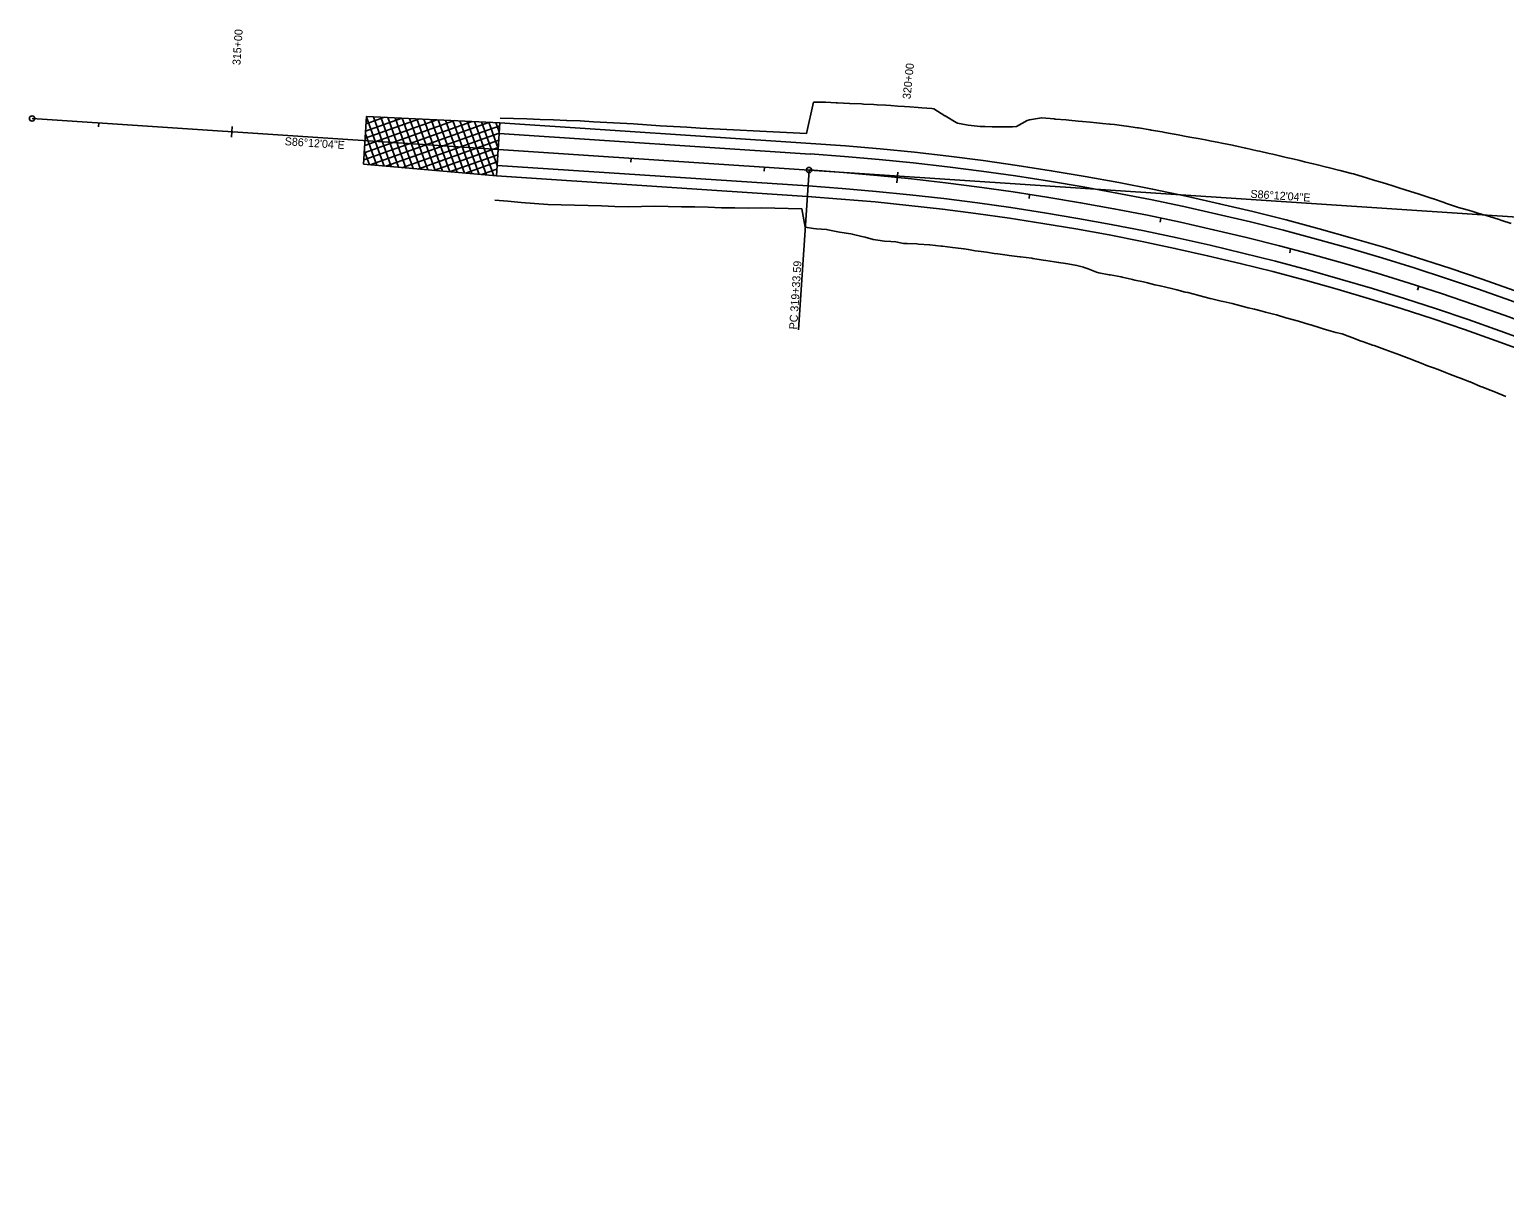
# Model space of a CAD drawing. Extents: x 881426 to 887360, y 1564404 to 1567430.
# Drawn here: x 881426 to 882531, y 1566404 to 1567265 of the extents above; entities that cross this region are included whole.
import ezdxf

# ---------------------------------------------------------------- set-up
doc = ezdxf.new("R2010")
doc.units = 0
for name, color, linetype in [('R_Axis', 7, 'Continuous'), ('R_Horz Alg', 7, 'Continuous'), ('R_Horz Alg Annot', 7, 'Continuous'), ('R_Proposed Const Limits_Fill', 7, 'Continuous'), ('R_Proposed Road_Lane', 7, 'Continuous'), ('R_Proposed Road_Shoulder', 7, 'Continuous')]:
    doc.layers.add(name, color=color, linetype=linetype)

msp = doc.modelspace()

# ---------------------------------------------------------------- linework, layer by layer
at = {"layer": 'R_Axis'}
for p, q in [((881676.1, 1567167.2), (881757.3, 1567196.1)), ((881676.4, 1567172.6), (881744.1, 1567196.7)), ((881676.8, 1567178.1), (881731, 1567197.3)), ((881677.1, 1567183.5), (881717.9, 1567198)), ((881677.5, 1567188.9), (881704.7, 1567198.6)), ((881677.9, 1567194.4), (881691.6, 1567199.2)), ((881678.2, 1567199.8), (881678.5, 1567199.9)), ((881691.3, 1567162.6), (881678.2, 1567199.3)), ((881696.7, 1567162.2), (881683.4, 1567199.6)), ((881702.2, 1567161.7), (881688.8, 1567199.4)), ((881707.7, 1567161.2), (881694.2, 1567199.1)), ((881713.2, 1567160.7), (881699.6, 1567198.9)), ((881718.7, 1567160.2), (881705, 1567198.6)), ((881724.1, 1567159.7), (881710.4, 1567198.3)), ((881729.6, 1567159.2), (881715.8, 1567198.1)), ((881735.1, 1567158.7), (881721.2, 1567197.8)), ((881740.6, 1567158.3), (881726.6, 1567197.6)), ((881746.1, 1567157.8), (881732, 1567197.3)), ((881751.5, 1567157.3), (881737.4, 1567197)), ((881757, 1567156.8), (881742.8, 1567196.8)), ((881762.5, 1567156.3), (881748.2, 1567196.5)), ((881768, 1567155.8), (881753.6, 1567196.3)), ((881685.8, 1567163.1), (881677.4, 1567186.8)), ((881680.8, 1567163.6), (881770.4, 1567195.5)), ((881692.7, 1567162.5), (881778, 1567192.8)), ((881704.7, 1567161.4), (881777.6, 1567187.4)), ((881773.5, 1567155.3), (881759, 1567196)), ((881776, 1567163.1), (881764.4, 1567195.7)), ((881776.8, 1567175.7), (881769.8, 1567195.5)), ((881777.7, 1567188.2), (881775.2, 1567195.2)), ((881680.3, 1567163.6), (881676.5, 1567174.2)), ((881716.6, 1567160.4), (881777.3, 1567182)), ((881728.6, 1567159.3), (881776.9, 1567176.5)), ((881740.5, 1567158.3), (881776.5, 1567171.1)), ((881752.4, 1567157.2), (881776.2, 1567165.7)), ((881764.4, 1567156.2), (881775.8, 1567160.2))]:
    msp.add_line(p, q, dxfattribs=at)
at = {"layer": 'R_Horz Alg'}
msp.add_line((881427.5, 1567198.3), (882009.9, 1567159.6), dxfattribs=at)
msp.add_arc((881883.4, 1565254), 1909.9, 37.4722, 86.2011, dxfattribs=at)
at = {"layer": 'R_Horz Alg Annot'}
msp.add_line((882009.9, 1567159.6), (882872.9, 1567102.3), dxfattribs=at)
for points in [[(881477.3, 1567192), (881477.5, 1567195)], [(881577.5, 1567192.4), (881577, 1567184.4)], [(881676.8, 1567178.8), (881677, 1567181.7)], [(881776.6, 1567172.1), (881776.8, 1567175.1)], [(881876.4, 1567165.5), (881876.6, 1567168.5)], [(881976.2, 1567158.9), (881976.4, 1567161.9)], [(882009.9, 1567159.6), (882001.9, 1567039.9)], [(882076.5, 1567158.1), (882075.7, 1567150.1)], [(882174.8, 1567138.4), (882175.2, 1567141.4)], [(882273, 1567120.6), (882273.6, 1567123.5)], [(882370.2, 1567097.7), (882370.9, 1567100.6)], [(882466, 1567069.6), (882466.9, 1567072.5)]]:
    msp.add_lwpolyline(points, dxfattribs=at)
for centre in [(881427.5, 1567198.3), (882009.9, 1567159.6)]:
    msp.add_circle(centre, 2, dxfattribs=at)
at = {"layer": 'R_Proposed Const Limits_Fill'}
for points in [[(881778.4, 1567198.6), (881788.4, 1567198.3), (881798.4, 1567198), (881808.4, 1567197.6), (881818.4, 1567197.3), (881828.2, 1567196.9), (881828.4, 1567196.9), (881838.4, 1567196.5), (881848.3, 1567195.8), (881858.3, 1567195.4), (881868.3, 1567194.9), (881878.3, 1567194.3), (881888.3, 1567193.5), (881898.2, 1567192.8), (881908.2, 1567192.3), (881918.2, 1567191.8), (881928.2, 1567191.1), (881938.2, 1567190.5), (881948.2, 1567190.1), (881958.2, 1567189.6), (881968.1, 1567189), (881978.1, 1567188.5), (881988.1, 1567188), (881998.1, 1567187.6), (882008.1, 1567187.1), (882013.3, 1567210.5), (882019.9, 1567210.4), (882022.3, 1567210.4), (882030.1, 1567210.1), (882031.3, 1567210), (882040.3, 1567209.6), (882040.4, 1567209.6), (882049.3, 1567209.2), (882050.7, 1567209.1), (882058.4, 1567208.7), (882060.9, 1567208.6), (882067.4, 1567208.2), (882071.2, 1567208), (882076.4, 1567207.6), (882081.5, 1567207.3), (882085.4, 1567207), (882091.7, 1567206.5), (882094.4, 1567206.3), (882102, 1567205.7), (882103.4, 1567205.6), (882111.7, 1567200.4), (882111.9, 1567200.2), (882120.3, 1567195.2), (882121.3, 1567194.7), (882129.2, 1567193.4), (882131.5, 1567193.1), (882138.1, 1567192.2), (882141.7, 1567192.2), (882147.1, 1567192.1), (882152, 1567192.1), (882156.2, 1567192.1), (882162.3, 1567192.1), (882165.3, 1567192.2), (882173.4, 1567196.9), (882175.2, 1567197.4), (882184.1, 1567198.7), (882184.5, 1567198.7), (882193.6, 1567198), (882194.4, 1567197.9), (882202.6, 1567197.2), (882204.7, 1567197), (882211.7, 1567196.4), (882215, 1567196.1), (882220.7, 1567195.5), (882225.3, 1567195.1), (882229.8, 1567194.6), (882235.2, 1567194.1), (882235.6, 1567194.1), (882238.8, 1567193.7), (882245.9, 1567192.8), (882247.8, 1567192.5), (882256.1, 1567191.3), (882256.8, 1567191.2), (882265.7, 1567189.7), (882266.3, 1567189.6), (882274.7, 1567188.2), (882276.5, 1567187.8), (882283.6, 1567186.6), (882286.7, 1567186), (882292.5, 1567184.9), (882296.8, 1567184.1), (882301.5, 1567183.3), (882307, 1567182.2), (882310.4, 1567181.5), (882317.1, 1567180.2), (882319.3, 1567179.8), (882327.3, 1567178.2), (882328.2, 1567178), (882337, 1567176.1), (882337.4, 1567176), (882345.9, 1567174.1), (882347.5, 1567173.8), (882354.8, 1567172.1), (882357.6, 1567171.5), (882363.6, 1567170.1), (882367.6, 1567169.1), (882372.5, 1567168), (882377.7, 1567166.8), (882381.3, 1567165.9), (882387.8, 1567164.3), (882390.1, 1567163.7), (882397.8, 1567161.8), (882399, 1567161.6), (882407.8, 1567159.4), (882407.9, 1567159.3), (882416.6, 1567157.1), (882417.9, 1567156.7), (882425.3, 1567154.5), (882427.8, 1567153.8), (882434, 1567151.9), (882437.7, 1567150.8), (882442.7, 1567149.2), (882447.6, 1567147.7), (882451.3, 1567146.5), (882457.5, 1567144.6), (882460, 1567143.8), (882467.3, 1567141.5), (882468.7, 1567141), (882477.1, 1567138.2), (882477.3, 1567138.2), (882485.9, 1567135.2), (882486.9, 1567134.9), (882494.5, 1567132.3), (882496.7, 1567131.6), (882503.2, 1567129.7), (882506.7, 1567128.7), (882511.9, 1567127.1), (882516.6, 1567125.7), (882520.6, 1567124.5), (882526.5, 1567122.7), (882529.3, 1567121.8), (882536.3, 1567119.5)], [(881774.3, 1567137), (881784.2, 1567136.2), (881794.2, 1567135.4), (881804.2, 1567134.6), (881814.2, 1567133.9), (881824, 1567133.6), (881824.2, 1567133.6), (881834.2, 1567133.3), (881844.2, 1567133), (881854.2, 1567132.7), (881864.2, 1567132.4), (881874.2, 1567132.1), (881884.2, 1567132.4), (881894.2, 1567132.5), (881904.3, 1567132.3), (881914.3, 1567132.1), (881924.3, 1567132), (881934.3, 1567131.8), (881944.3, 1567131.4), (881954.3, 1567131.3), (881964.3, 1567131.1), (881974.3, 1567131.2), (881984.3, 1567131), (881994.3, 1567130.8), (882004.4, 1567130.6), (882007, 1567116.8), (882013.3, 1567115.8), (882015.6, 1567115.6), (882023, 1567115.1), (882024.1, 1567114.9), (882032.6, 1567113.2), (882032.6, 1567113.1), (882041.1, 1567111.8), (882042.3, 1567111.7), (882049.5, 1567109.9), (882051.9, 1567109.3), (882057.9, 1567107.7), (882061.5, 1567107.2), (882066.4, 1567106.4), (882071.2, 1567106), (882074.9, 1567105.8), (882080.8, 1567104.7), (882083.4, 1567104.6), (882090.6, 1567104.3), (882092, 1567104.2), (882100.3, 1567103.6), (882100.5, 1567103.6), (882109, 1567102.7), (882110, 1567102.6), (882117.5, 1567101.6), (882119.7, 1567101.4), (882126, 1567100.6), (882129.4, 1567100), (882134.5, 1567099.2), (882139, 1567098.6), (882142.9, 1567098), (882148.7, 1567097.2), (882151.4, 1567096.8), (882158.3, 1567095.9), (882159.9, 1567095.7), (882168, 1567094.7), (882168.4, 1567094.6), (882176.9, 1567093.5), (882177.7, 1567093.3), (882185.4, 1567092.2), (882187.3, 1567091.9), (882193.8, 1567090.9), (882197, 1567090.4), (882202.3, 1567089.5), (882206.6, 1567088.8), (882210.7, 1567088.1), (882215.7, 1567086.8), (882216.1, 1567086.7), (882219, 1567085.6), (882225.4, 1567083.1), (882227.1, 1567082.7), (882234.9, 1567081.1), (882235.5, 1567081), (882243.9, 1567079.5), (882244.5, 1567079.3), (882252.3, 1567077.5), (882254, 1567077.1), (882260.7, 1567075.8), (882263.5, 1567075.1), (882269, 1567073.7), (882273, 1567072.8), (882277.3, 1567071.9), (882282.5, 1567070.6), (882285.6, 1567069.8), (882291.9, 1567068.2), (882293.9, 1567067.8), (882301.4, 1567065.9), (882302.2, 1567065.7), (882310.5, 1567063.4), (882310.8, 1567063.4), (882318.8, 1567061.4), (882320.2, 1567061.1), (882327.1, 1567059.5), (882329.7, 1567058.8), (882335.4, 1567057.3), (882339.1, 1567056.4), (882343.7, 1567055.3), (882348.6, 1567054), (882352, 1567053.2), (882358, 1567051.6), (882360.2, 1567051), (882367.4, 1567048.9), (882368.4, 1567048.6), (882376.7, 1567046.4), (882376.8, 1567046.3), (882384.8, 1567043.9), (882386.1, 1567043.5), (882393, 1567041.3), (882395.4, 1567040.6), (882401.2, 1567038.8), (882404.7, 1567037.8), (882409.5, 1567036.9), (882414, 1567035.1), (882417.5, 1567033.8), (882423.1, 1567031.6), (882425.5, 1567030.8), (882432.3, 1567028.4), (882433.6, 1567028), (882441.5, 1567025.2), (882441.6, 1567025.1), (882449.7, 1567022.2), (882450.6, 1567021.8), (882457.7, 1567019.2), (882459.8, 1567018.4), (882465.6, 1567016.1), (882468.8, 1567014.9), (882473.6, 1567013), (882477.9, 1567011.4), (882481.6, 1567010.1), (882487, 1567008), (882489.6, 1567007), (882496, 1567004.4), (882497.5, 1567003.8), (882505.1, 1567000.9), (882505.5, 1567000.8), (882513.3, 1566997.5), (882514.1, 1566997.2), (882521.3, 1566994.4), (882523.1, 1566993.6), (882529.2, 1566991.2), (882532.1, 1566990)]]:
    msp.add_lwpolyline(points, dxfattribs=at)
at = {"layer": 'R_Proposed Road_Lane'}
for p, q in [((881776, 1567163.1), (881777.6, 1567187.1)), ((881777.6, 1567187.1), (882010.7, 1567171.6)), ((881776, 1567163.1), (882009.1, 1567147.7))]:
    msp.add_line(p, q, dxfattribs=at)
for radius in [1921.9, 1897.9]:
    msp.add_arc((881883.4, 1565254), radius, 37.4722, 86.2011, dxfattribs=at)
at = {"layer": 'R_Proposed Road_Shoulder'}
for p, q in [((881675.9, 1567164), (881678.2, 1567199.9)), ((881678.2, 1567199.9), (881778.1, 1567195.1)), ((881777.6, 1567187.1), (881778.1, 1567195.1)), ((881778.1, 1567195.1), (882011.2, 1567179.6)), ((881675.9, 1567164), (881775.5, 1567155.2)), ((881775.5, 1567155.2), (881776, 1567163.1)), ((881775.5, 1567155.2), (882008.6, 1567139.7))]:
    msp.add_line(p, q, dxfattribs=at)
for radius in [1929.9, 1909.9, 1889.9]:
    msp.add_arc((881883.4, 1565254), radius, 37.4722, 86.2011, dxfattribs=at)

# ---------------------------------------------------------------- texts
at = {"layer": 'R_Horz Alg Annot'}
for s, rotation, p in [('315+00', 86.2011, (881583.6, 1567238.1)), ('320+00', 84.2089, (882085.9, 1567212.6)), ('S86%%d12\'04"E', 356.2011, (881616.7, 1567178.3)), ('S86%%d12\'04"E', 356.2011, (882340.6, 1567138.9)), ('PC 319+33.59', 86.2011, (882000.9, 1567040))]:
    msp.add_text(s, height=6, rotation=rotation, dxfattribs=at).set_placement(p)

doc.saveas('drawing.dxf')
